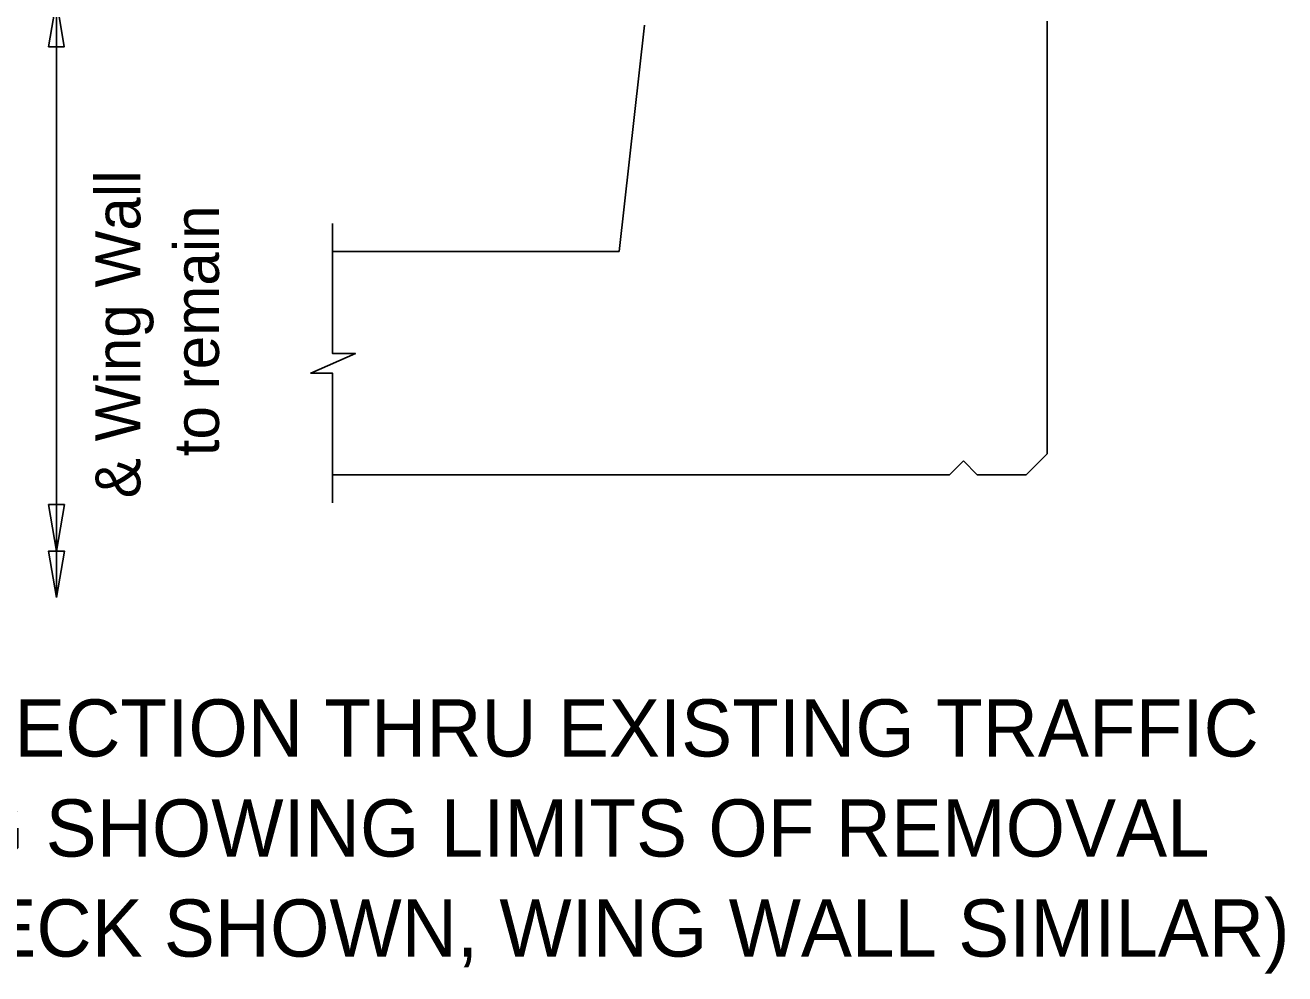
# Model space of a CAD drawing. Extents: x 0.1 to 40.1, y 0.1 to 25.4.
# Drawn here: x 19.74 to 25.38, y 0.54 to 4.79 of the extents above; entities that cross this region are included whole.
import ezdxf

# ---------------------------------------------------------------- set-up
doc = ezdxf.new("R2010")
doc.units = 0
doc.layers.add('Dimension', color=7, linetype='Continuous')
doc.layers.add('TrafBarrierConc', color=7, linetype='Continuous')

# ---------------------------------------------------------------- blocks, each defined once
blk = doc.blocks.new('Terminator-Arrow')
at = {"layer": 'Dimension'}
blk.add_lwpolyline([(0, 0), (-0.00041, 0.000069), (-0.00041, -0.000069)], close=True, dxfattribs=at)

msp = doc.modelspace()

# ---------------------------------------------------------------- linework, layer by layer
at = {"layer": 'Dimension'}
for p, q in [((19.8817, 8.2753), (19.8817, 3.7752)), ((19.8816, 4.9), (19.8816, 2.2259))]:
    msp.add_line(p, q, dxfattribs=at)
msp.add_lwpolyline([(21.1171, 3.9003), (21.1171, 3.3194), (21.2204, 3.3194), (21.0204, 3.2311), (21.1171, 3.2311), (21.1171, 2.6502)], dxfattribs=at)
for points in [[(19.8815, 2.4342), (19.9168, 2.6425), (19.8462, 2.6425)], [(19.8815, 2.226), (19.9168, 2.4342), (19.8462, 2.4342)]]:
    msp.add_lwpolyline(points, close=True, dxfattribs=at)
at = {"layer": 'TrafBarrierConc'}
for p, q in [((24.317, 2.8689), (24.317, 4.8065)), ((22.5138, 4.7891), (22.4012, 3.7753)), ((21.1171, 3.7753), (22.4012, 3.7753)), ((23.8795, 2.7752), (23.942, 2.8377)), ((23.942, 2.8377), (24.0045, 2.7752)), ((24.317, 2.869), (24.2232, 2.7752)), ((23.8795, 2.7752), (21.1171, 2.7752)), ((24.2232, 2.7752), (24.0045, 2.7752))]:
    msp.add_line(p, q, dxfattribs=at)

# ---------------------------------------------------------------- block references
at = {"layer": 'Dimension', "xscale": 506.22200000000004, "yscale": -511.77976190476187, "rotation": 90}
msp.add_blockref('Terminator-Arrow', (19.8814, 4.8998), dxfattribs=at)

# ---------------------------------------------------------------- texts
at = {"layer": 'Dimension'}
for s, p in [('& Wing Wall', (20.257, 2.6706)), ('to remain', (20.609, 2.8586))]:
    msp.add_text(s, height=0.2016, rotation=90, dxfattribs=at).set_placement(p)
for s, p in [('TYPICAL SECTION THRU EXISTING TRAFFIC ', (17.9422, 1.5141)), ('RAILING SHOWING LIMITS OF REMOVAL', (18.3684, 1.0661)), ('(BRIDGE DECK SHOWN, WING WALL SIMILAR)', (17.7945, 0.6181))]:
    msp.add_text(s, height=0.256, dxfattribs=at).set_placement(p)

doc.saveas('drawing.dxf')
